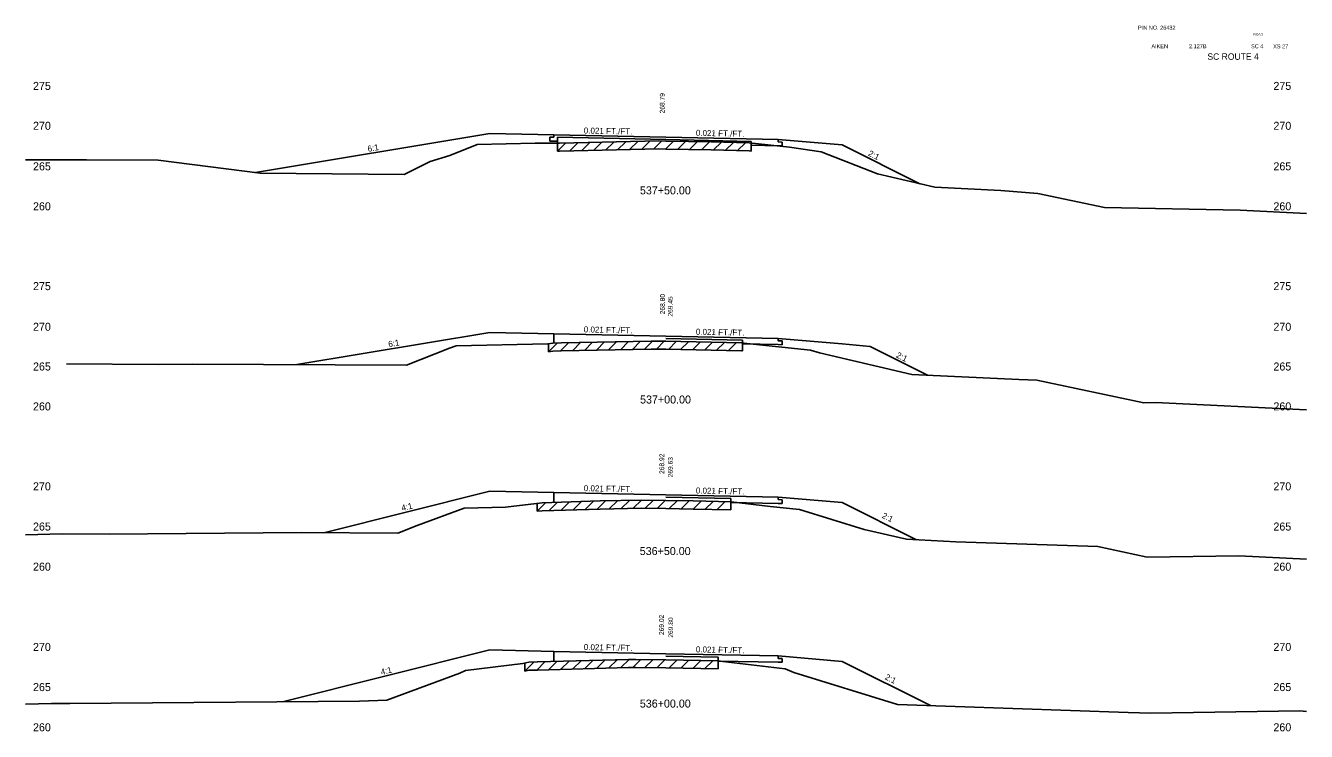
# Model space of a CAD drawing. Extents: x 883 to 1160, y 1002 to 4323.
# Drawn here: x 1000 to 1160, y 4005.1 to 4093.2 of the extents above; entities that cross this region are included whole.
import ezdxf

# ---------------------------------------------------------------- set-up
doc = ezdxf.new("R2010")
doc.units = 0
for name, color, linetype in [('Level 1', 7, 'Continuous'), ('Level 10', 7, 'Continuous'), ('Level 11', 7, 'Continuous'), ('Level 12', 7, 'Continuous'), ('Level 3', 7, 'Continuous'), ('Level 32', 7, 'Continuous'), ('Level 53', 7, 'Continuous'), ('Level 59', 7, 'Continuous'), ('Level 6', 7, 'Continuous'), ('Level 60', 7, 'Continuous'), ('Level 61', 7, 'Continuous'), ('Level 7', 7, 'Continuous')]:
    doc.layers.add(name, color=color, linetype=linetype)

msp = doc.modelspace()

# ---------------------------------------------------------------- linework, layer by layer
at = {"layer": 'Level 11'}
for p, q in [((1066, 4079.27), (1065.5, 4079.28)), ((1065.5, 4079.28), (1065.5, 4078.8)), ((1065.5, 4078.8), (1066, 4078.79)), ((1066, 4079.57), (1066, 4079.27)), ((1094, 4078.68), (1094, 4078.98)), ((1094.5, 4078.67), (1094, 4078.68)), ((1094.5, 4078.19), (1094.5, 4078.67)), ((1094, 4078.2), (1094.5, 4078.19)), ((1066, 4053.57), (1066, 4054.74)), ((1094, 4053.86), (1094, 4054.16)), ((1094.5, 4053.85), (1094, 4053.86)), ((1094, 4053.38), (1094.5, 4053.37)), ((1094.5, 4053.37), (1094.5, 4053.85)), ((1066, 4033.69), (1066, 4034.92)), ((1094, 4034.03), (1094, 4034.33)), ((1094.5, 4034.02), (1094, 4034.03)), ((1094.5, 4033.54), (1094.5, 4034.02)), ((1094, 4033.55), (1094.5, 4033.54)), ((1066, 4013.82), (1066, 4015.09)), ((1094, 4014.21), (1094, 4014.51)), ((1094.5, 4014.2), (1094, 4014.21)), ((1094, 4013.73), (1094.5, 4013.72)), ((1094.5, 4013.72), (1094.5, 4014.2))]:
    msp.add_line(p, q, dxfattribs=at)
at = {"layer": 'Level 12'}
for p, q in [((1066.44, 4078.78), (1066, 4078.79)), ((1066.44, 4078.52), (1066.44, 4078.78)), ((1090.64, 4078.54), (1090.64, 4078.27)), ((1090.64, 4078.27), (1094, 4078.2)), ((1089.55, 4053.6), (1089.55, 4053.47)), ((1089.55, 4053.47), (1094, 4053.38)), ((1088.11, 4033.77), (1088.11, 4033.68)), ((1088.11, 4033.68), (1094, 4033.55)), ((1086.5, 4013.91), (1086.5, 4013.88)), ((1086.5, 4013.88), (1094, 4013.73))]:
    msp.add_line(p, q, dxfattribs=at)
at = {"layer": 'Level 53'}
for p, q in [((1080, 4078.98), (1066.44, 4079.26)), ((1066.44, 4079.26), (1066.44, 4078.52)), ((1080, 4078.98), (1090.64, 4078.75)), ((1090.64, 4078.75), (1090.64, 4078.54)), ((1080, 4054.15), (1089.55, 4053.95)), ((1089.55, 4053.95), (1089.55, 4053.6)), ((1080, 4034.33), (1088.11, 4034.16)), ((1088.11, 4034.16), (1088.11, 4033.77)), ((1080, 4014.5), (1086.5, 4014.36)), ((1086.5, 4014.36), (1086.5, 4013.91))]:
    msp.add_line(p, q, dxfattribs=at)
at = {"layer": 'Level 59'}
for p, q in [((1066, 4079.57), (1080, 4079.28)), ((1080, 4079.28), (1094, 4078.98)), ((1066, 4054.74), (1080, 4054.45)), ((1080, 4054.45), (1094, 4054.16)), ((1066, 4034.92), (1080, 4034.63)), ((1080, 4034.63), (1094, 4034.33)), ((1066, 4015.09), (1080, 4014.8)), ((1080, 4014.8), (1094, 4014.51))]:
    msp.add_line(p, q, dxfattribs=at)
at = {"layer": 'Level 6'}
for p, q in [((1058, 4079.73), (1066, 4079.57)), ((1094, 4078.98), (1102, 4078.32)), ((1058, 4054.91), (1066, 4054.74)), ((1094, 4054.16), (1102, 4053.49)), ((1102, 4053.49), (1105.5, 4053.14)), ((1058, 4035.08), (1066, 4034.92)), ((1094, 4034.33), (1102, 4033.67)), ((1058, 4015.26), (1066, 4015.09)), ((1094, 4014.51), (1102, 4013.84))]:
    msp.add_line(p, q, dxfattribs=at)
at = {"layer": 'Level 60'}
for p, q in [((1056.41, 4078.36), (1063.66, 4078.51)), ((1063.66, 4078.51), (1066.69, 4078.52)), ((1066.69, 4078.52), (1073.81, 4078.68)), ((1073.81, 4078.68), (1079.09, 4078.81)), ((1079.09, 4078.81), (1080, 4078.79)), ((1080, 4078.79), (1085.64, 4078.68)), ((1085.64, 4078.68), (1090.4, 4078.57)), ((1090.4, 4078.57), (1095.42, 4078.04)), ((1050.55, 4076.26), (1053.01, 4077.01)), ((1053.01, 4077.01), (1056.41, 4078.36)), ((1095.42, 4078.04), (1099.4, 4077.46)), ((1099.4, 4077.46), (1106.44, 4074.69)), ((1000, 4076.46), (1007.62, 4076.46)), ((1007.62, 4076.46), (1016.54, 4076.4)), ((1016.54, 4076.4), (1029.3, 4074.78)), ((1047.27, 4074.62), (1050.55, 4076.26)), ((1029.3, 4074.78), (1047.27, 4074.62)), ((1106.44, 4074.69), (1113.6, 4073.02)), ((1113.6, 4073.02), (1121.82, 4072.62)), ((1121.82, 4072.62), (1126.47, 4072.25)), ((1126.47, 4072.25), (1134.79, 4070.51)), ((1134.79, 4070.51), (1151.71, 4070.16)), ((1151.71, 4070.16), (1160, 4069.75)), ((1047.6, 4050.81), (1052.94, 4052.94)), ((1052.94, 4052.94), (1053.77, 4053.25)), ((1053.77, 4053.25), (1065.22, 4053.48)), ((1065.22, 4053.48), (1065.86, 4053.56)), ((1065.86, 4053.56), (1066.89, 4053.59)), ((1066.89, 4053.59), (1078.14, 4053.83)), ((1078.14, 4053.83), (1079.05, 4053.82)), ((1079.05, 4053.82), (1080, 4053.8)), ((1080, 4053.8), (1089.42, 4053.61)), ((1089.42, 4053.61), (1090.09, 4053.53)), ((1090.09, 4053.53), (1098.06, 4052.69)), ((1098.06, 4052.69), (1099.16, 4052.35)), ((1099.16, 4052.35), (1110.71, 4049.66)), ((1005.12, 4050.98), (1016.56, 4050.92)), ((1016.56, 4050.92), (1020.8, 4050.96)), ((1020.8, 4050.96), (1047.6, 4050.81)), ((1110.71, 4049.66), (1124.09, 4049.03)), ((1124.09, 4049.03), (1126.31, 4048.95)), ((1126.31, 4048.95), (1139.68, 4046.13)), ((1139.68, 4046.13), (1141.17, 4046.15)), ((1141.17, 4046.15), (1160, 4045.22)), ((1059.95, 4033.09), (1064.53, 4033.65)), ((1064.53, 4033.65), (1071.77, 4033.86)), ((1071.77, 4033.86), (1076.89, 4033.97)), ((1076.89, 4033.97), (1080, 4033.92)), ((1080, 4033.92), (1083.41, 4033.86)), ((1083.41, 4033.86), (1088.15, 4033.77)), ((1088.15, 4033.77), (1093.03, 4033.18)), ((1048.9, 4030.81), (1054.78, 4032.98)), ((1054.78, 4032.98), (1059.95, 4033.09)), ((1093.03, 4033.18), (1096.68, 4032.79)), ((1096.68, 4032.79), (1104.76, 4030.31)), ((1046.5, 4029.85), (1048.9, 4030.81)), ((1000, 4029.64), (1004.57, 4029.74)), ((1004.57, 4029.74), (1010.44, 4029.71)), ((1010.44, 4029.71), (1034.48, 4029.91)), ((1034.48, 4029.91), (1046.5, 4029.85)), ((1104.76, 4030.31), (1110.06, 4029.08)), ((1110.06, 4029.08), (1116.21, 4028.78)), ((1116.21, 4028.78), (1133.96, 4028.16)), ((1133.96, 4028.16), (1140.13, 4026.86)), ((1140.13, 4026.86), (1151.56, 4027.03)), ((1151.56, 4027.03), (1160, 4026.61)), ((1054.94, 4012.7), (1062.1, 4013.58)), ((1062.1, 4013.58), (1062.87, 4013.74)), ((1062.87, 4013.74), (1063.93, 4013.76)), ((1063.93, 4013.76), (1075.31, 4014.09)), ((1075.31, 4014.09), (1076.22, 4014.08)), ((1076.22, 4014.08), (1080, 4014.02)), ((1080, 4014.02), (1086.55, 4013.91)), ((1086.55, 4013.91), (1087.12, 4013.83)), ((1087.12, 4013.83), (1094.89, 4012.89)), ((1094.89, 4012.89), (1095.97, 4012.44)), ((1045.11, 4008.98), (1054.23, 4012.36)), ((1054.23, 4012.36), (1054.94, 4012.7)), ((1095.97, 4012.44), (1108.9, 4008.47)), ((1000, 4008.51), (1003.23, 4008.58)), ((1003.23, 4008.58), (1005.54, 4008.56)), ((1005.54, 4008.56), (1041.72, 4008.86)), ((1041.72, 4008.86), (1045.11, 4008.98)), ((1108.9, 4008.47), (1137.73, 4007.46)), ((1137.73, 4007.46), (1140.55, 4007.38)), ((1140.55, 4007.38), (1159.2, 4007.67)), ((1159.2, 4007.67), (1160, 4007.59))]:
    msp.add_line(p, q, dxfattribs=at)
at = {"layer": 'Level 61'}
for p, q in [((1067.46, 4078.54), (1066.44, 4077.52)), ((1066.44, 4078.52), (1066.44, 4077.52)), ((1068.97, 4078.57), (1067.94, 4077.55)), ((1070.47, 4078.61), (1069.44, 4077.58)), ((1071.97, 4078.64), (1070.94, 4077.62)), ((1073.47, 4078.67), (1072.44, 4077.65)), ((1074.97, 4078.71), (1073.94, 4077.68)), ((1076.47, 4078.74), (1075.44, 4077.72)), ((1077.97, 4078.78), (1076.95, 4077.76)), ((1079.45, 4078.8), (1078.45, 4077.79)), ((1080.93, 4078.77), (1079.95, 4077.79)), ((1082.43, 4078.75), (1081.45, 4077.76)), ((1083.93, 4078.72), (1082.95, 4077.74)), ((1085.43, 4078.69), (1084.45, 4077.71)), ((1086.92, 4078.65), (1085.95, 4077.68)), ((1088.42, 4078.62), (1087.45, 4077.64)), ((1089.92, 4078.58), (1088.95, 4077.6)), ((1090.64, 4077.54), (1090.64, 4078.54)), ((1066.44, 4077.52), (1066.69, 4077.52)), ((1066.69, 4077.52), (1073.81, 4077.68)), ((1073.81, 4077.68), (1079.09, 4077.81)), ((1079.09, 4077.81), (1080, 4077.79)), ((1080, 4077.79), (1085.64, 4077.68)), ((1085.64, 4077.68), (1090.4, 4077.57)), ((1090.4, 4077.57), (1090.64, 4077.54)), ((1066.39, 4053.58), (1065.31, 4052.5)), ((1065.31, 4053.5), (1065.31, 4052.5)), ((1067.83, 4053.61), (1066.81, 4052.59)), ((1066.89, 4052.59), (1078.14, 4052.83)), ((1069.33, 4053.65), (1068.31, 4052.62)), ((1070.83, 4053.68), (1069.81, 4052.66)), ((1072.33, 4053.71), (1071.31, 4052.69)), ((1073.83, 4053.74), (1072.81, 4052.72)), ((1075.33, 4053.77), (1074.31, 4052.75)), ((1076.83, 4053.8), (1075.81, 4052.78)), ((1078.33, 4053.83), (1077.31, 4052.81)), ((1078.14, 4052.83), (1079.05, 4052.82)), ((1079.79, 4053.8), (1078.81, 4052.82)), ((1079.05, 4052.82), (1080, 4052.8)), ((1081.29, 4053.77), (1080.31, 4052.79)), ((1082.79, 4053.74), (1081.81, 4052.76)), ((1084.3, 4053.71), (1083.31, 4052.73)), ((1085.8, 4053.69), (1084.81, 4052.7)), ((1087.3, 4053.66), (1086.32, 4052.68)), ((1088.8, 4053.63), (1087.82, 4052.65)), ((1089.55, 4052.6), (1089.55, 4053.6)), ((1065.31, 4052.5), (1065.86, 4052.56)), ((1065.86, 4052.56), (1066.89, 4052.59)), ((1080, 4052.8), (1089.42, 4052.61)), ((1089.42, 4052.61), (1089.55, 4052.6)), ((1064.99, 4033.66), (1063.9, 4032.57)), ((1066.43, 4033.7), (1065.4, 4032.67)), ((1067.93, 4033.75), (1066.9, 4032.72)), ((1069.43, 4033.79), (1068.4, 4032.76)), ((1070.93, 4033.83), (1069.9, 4032.8)), ((1072.43, 4033.87), (1071.41, 4032.85)), ((1073.93, 4033.9), (1072.91, 4032.88)), ((1075.43, 4033.94), (1074.41, 4032.91)), ((1076.93, 4033.97), (1075.91, 4032.95)), ((1078.39, 4033.94), (1077.41, 4032.96)), ((1079.89, 4033.92), (1078.91, 4032.93)), ((1081.39, 4033.89), (1080.41, 4032.91)), ((1082.89, 4033.87), (1081.91, 4032.89)), ((1084.39, 4033.84), (1083.41, 4032.86)), ((1085.89, 4033.81), (1084.91, 4032.83)), ((1087.39, 4033.78), (1086.41, 4032.8)), ((1088.11, 4032.77), (1088.11, 4033.77)), ((1063.9, 4033.57), (1063.9, 4032.57)), ((1063.9, 4032.57), (1064.53, 4032.65)), ((1064.53, 4032.65), (1071.77, 4032.86)), ((1071.77, 4032.86), (1076.89, 4032.97)), ((1076.89, 4032.97), (1080, 4032.92)), ((1080, 4032.92), (1083.41, 4032.86)), ((1083.41, 4032.86), (1088.11, 4032.77)), ((1063.47, 4013.75), (1062.35, 4012.63)), ((1062.35, 4013.63), (1062.35, 4012.63)), ((1064.88, 4013.79), (1063.85, 4012.76)), ((1063.93, 4012.76), (1075.31, 4013.09)), ((1066.38, 4013.84), (1065.35, 4012.81)), ((1067.89, 4013.88), (1066.85, 4012.85)), ((1069.39, 4013.92), (1068.36, 4012.89)), ((1070.89, 4013.97), (1069.86, 4012.94)), ((1072.39, 4014.01), (1071.36, 4012.98)), ((1073.89, 4014.05), (1072.86, 4013.02)), ((1075.39, 4014.09), (1074.36, 4013.07)), ((1075.31, 4013.09), (1076.22, 4013.08)), ((1076.84, 4014.07), (1075.86, 4013.08)), ((1076.22, 4013.08), (1080, 4013.02)), ((1078.35, 4014.04), (1077.36, 4013.06)), ((1079.85, 4014.02), (1078.86, 4013.04)), ((1080, 4013.02), (1086.5, 4012.91)), ((1081.35, 4014), (1080.36, 4013.01)), ((1082.85, 4013.97), (1081.86, 4012.99)), ((1084.35, 4013.95), (1083.36, 4012.96)), ((1085.85, 4013.92), (1084.87, 4012.94)), ((1086.5, 4012.91), (1086.5, 4013.91)), ((1062.35, 4012.63), (1062.87, 4012.74)), ((1062.87, 4012.74), (1063.93, 4012.76))]:
    msp.add_line(p, q, dxfattribs=at)
at = {"layer": 'Level 7'}
for p, q in [((1028.71, 4074.85), (1058, 4079.73)), ((1102, 4078.32), (1111.71, 4073.46)), ((1033.87, 4050.89), (1058, 4054.91)), ((1105.5, 4053.14), (1112.65, 4049.57)), ((1037.25, 4029.9), (1058, 4035.08)), ((1102, 4033.67), (1111.3, 4029.02)), ((1032.08, 4008.78), (1058, 4015.26)), ((1102, 4013.84), (1113.03, 4008.33))]:
    msp.add_line(p, q, dxfattribs=at)

# ---------------------------------------------------------------- texts
at = {"layer": 'Level 1'}
for s, height, p in [('PIN NO. 26432', 0.5, (1138.97, 4092.7)), ('AIKEN', 0.5, (1140.64, 4090.38)), (' 2.127B', 0.5, (1145.15, 4090.38)), ('SC ROUTE 4', 0.8, (1147.63, 4088.94)), ('SC 4', 0.5, (1153.09, 4090.38)), ('XS 27', 0.5, (1155.85, 4090.37)), ('537+50.00', 1, (1076.74, 4072.14)), ('537+00.00', 1, (1076.76, 4046.03)), ('536+50.00', 1, (1076.72, 4027.11)), ('536+00.00', 1, (1076.73, 4008.07))]:
    msp.add_text(s, height=height, dxfattribs=at).set_placement(p)
at = {"layer": 'Level 10'}
for s, p in [('268.79', (1079.83, 4082.25)), ('268.80', (1079.86, 4057.17)), ('268.92', (1079.78, 4037.24)), ('269.02', (1079.74, 4017.12))]:
    msp.add_text(s, height=0.6, rotation=90, dxfattribs=at).set_placement(p)
at = {"layer": 'Level 3'}
for s, height, p in [('ROAD', 0.3, (1153.38, 4091.97)), (' 275', 1, (1000.55, 4085.18)), (' 275', 1, (1155.51, 4085.18)), (' 270', 1, (1000.55, 4080.2)), (' 270', 1, (1155.51, 4080.2)), (' 265', 1, (1000.55, 4075.14)), (' 265', 1, (1155.51, 4075.14)), (' 260', 1, (1000.55, 4070.15)), (' 260', 1, (1155.51, 4070.15)), (' 275', 1, (1000.55, 4060.18)), (' 275', 1, (1155.51, 4060.18)), (' 270', 1, (1000.55, 4055.11)), (' 270', 1, (1155.51, 4055.11)), (' 265', 1, (1000.55, 4050.15)), (' 265', 1, (1155.51, 4050.15)), (' 260', 1, (1000.55, 4045.17)), (' 260', 1, (1155.51, 4045.17)), (' 270', 1, (1000.55, 4035.19)), (' 270', 1, (1155.51, 4035.19)), (' 265', 1, (1000.55, 4030.17)), (' 265', 1, (1155.51, 4030.17)), (' 260', 1, (1000.55, 4025.16)), (' 260', 1, (1155.51, 4025.16)), (' 270', 1, (1000.55, 4015.14)), (' 270', 1, (1155.51, 4015.14)), (' 265', 1, (1000.55, 4010.13)), (' 265', 1, (1155.51, 4010.13)), (' 260', 1, (1000.55, 4005.11)), (' 260', 1, (1155.51, 4005.11))]:
    msp.add_text(s, height=height, dxfattribs=at).set_placement(p)
at = {"layer": 'Level 32'}
for s, rotation, p in [('0.021 FT./FT.', 358.8084, (1069.72, 4079.74)), ('0.021 FT./FT.', 358.8084, (1083.72, 4079.45)), ('6:1', 9.4623, (1042.79, 4077.45)), ('2:1', 333.435, (1105.18, 4077.01)), ('0.021 FT./FT.', 358.8084, (1069.72, 4054.91)), ('0.021 FT./FT.', 358.8084, (1083.72, 4054.62)), ('6:1', 9.4623, (1045.37, 4053.06)), ('2:1', 333.435, (1108.68, 4051.83)), ('0.021 FT./FT.', 358.8084, (1069.72, 4035.09)), ('0.021 FT./FT.', 358.8084, (1083.72, 4034.8)), ('4:1', 14.0362, (1047.05, 4032.6)), ('2:1', 333.435, (1106.9, 4031.79)), ('0.021 FT./FT.', 358.8084, (1069.72, 4015.26)), ('0.021 FT./FT.', 358.8084, (1083.72, 4014.97)), ('4:1', 14.0362, (1044.46, 4012.13)), ('2:1', 333.435, (1107.28, 4011.64))]:
    msp.add_text(s, height=0.75, rotation=rotation, dxfattribs=at).set_placement(p)
at = {"layer": 'Level 59'}
for s, p in [(' 269.45', (1080.84, 4056.65)), (' 269.63', (1080.85, 4036.58)), (' 269.80', (1080.88, 4016.57))]:
    msp.add_text(s, height=0.6, rotation=90, dxfattribs=at).set_placement(p)

doc.saveas('drawing.dxf')
